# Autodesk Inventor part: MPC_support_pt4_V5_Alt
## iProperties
Shininess: 64.0
Length Units: 11269
Angle Units: 11279
Time Units: 11290
Mass Units: 11283
Length Display Precision: 3
Angle Display Precision: 2
Compacted: True
Part Number: MPC_support_pt4_V5_Alt
Document SubType Name: Modeling
Created: 2004-08
Designer: John Blackburn
Manufacturer: Standard
Standards Organization: Custom
Material: Stainless Steel, Austenitic
Density: 0.0
Volumn: 0.0
Area: 0.0
PropertySet Name: Model Information
Control State: 0
Master: False
Checked Out: False
Author: John Blackburn
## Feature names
1. Extrusion1
2. Hole1
3. Hole2
4. Hole3
5. Chamfer1
6. Fillet1
7. Extrusion2
